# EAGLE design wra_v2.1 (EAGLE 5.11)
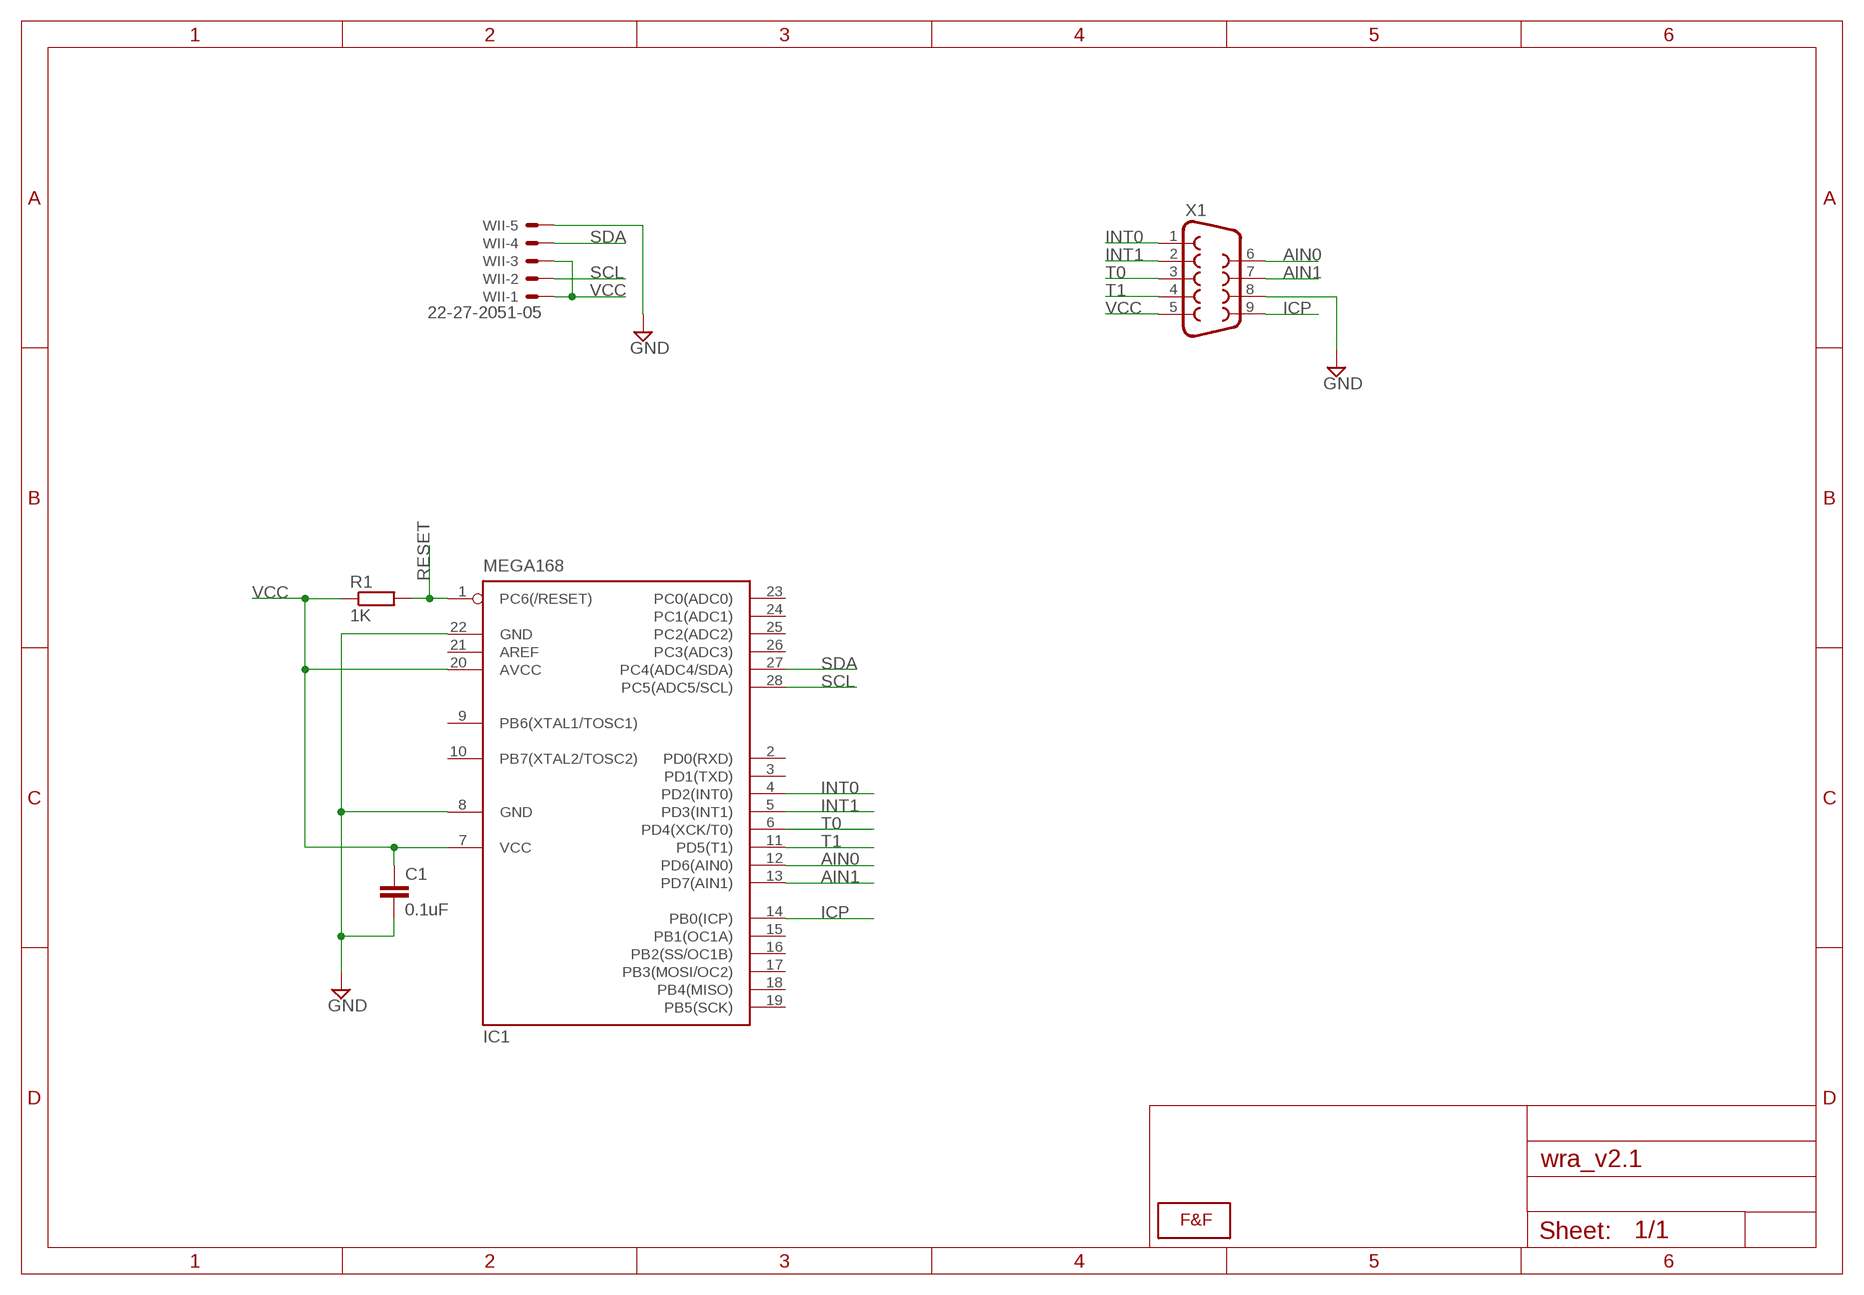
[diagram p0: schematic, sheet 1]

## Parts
C1  0.1uF  C-EU050-024X044  [C050-024X044]
IC1  MEGA168  MEGA8-P  [DIL28-3]
R1  1K  R-EU_0207/2V  [0207/2V]
U$1  LOGOLOGO_WITH_SMOKE_BIG  [LOGO_BIG]
WII  22-27-2051-05  [6410-05]
X1  DB9MALE  [DB9_MALE]

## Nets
AIN0: IC1.12(PD6(AIN0)) X1.6
AIN1: IC1.13(PD7(AIN1)) X1.7
GND: C1.2 IC1.8(GND) IC1.22(GND) WII.5 X1.8
ICP: IC1.14(PB0(ICP)) X1.9
INT0: IC1.4(PD2(INT0)) X1.1
INT1: IC1.5(PD3(INT1)) X1.2
RESET: IC1.1(PC6(/RESET)) R1.2
SCL: IC1.28(PC5(ADC5/SCL)) WII.2
SDA: IC1.27(PC4(ADC4/SDA)) WII.4
T0: IC1.6(PD4(XCK/T0)) X1.3
T1: IC1.11(PD5(T1)) X1.4
VCC: C1.1 IC1.7(VCC) IC1.20(AVCC) R1.1 WII.1 WII.3 X1.5
Unconnected: IC1.2(PD0(RXD)) IC1.3(PD1(TXD)) IC1.9(PB6(XTAL1/TOSC1)) IC1.10(PB7(XTAL2/TOSC2)) IC1.15(PB1(OC1A)) IC1.16(PB2(SS/OC1B)) IC1.17(PB3(MOSI/OC2)) IC1.18(PB4(MISO)) IC1.19(PB5(SCK)) IC1.21(AREF) IC1.23(PC0(ADC0)) IC1.24(PC1(ADC1)) IC1.25(PC2(ADC2)) IC1.26(PC3(ADC3))

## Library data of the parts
C1 = rcl:C-EU: CAPACITOR, European symbol
IC1 = atmel:MEGA8-P: MICROCONTROLLER 8 Kbytes FLASH, 1 kbytes SRAM, 512 bytes EEPROM, USART, 4-channel 10 bit ADC, 2-channel 8 bit ADC Pin compatible with Atmega48, ATMega88, ATMega168 Source: avr.lbr; OC_FARNELL: unknown; OC_NEWARK: unknown
R1 = rcl:R-EU_: RESISTOR, European symbol
U$1 = F&F:LOGO: Faísca e Fumaça Logo
WII = con-molex:22-?-05: CONNECTOR wire to board 2.54 mm (.1 inch) pitch header; OC_FARNELL: unknown; OC_NEWARK: unknown
X1 = SparkFun:DB9: DB9 Connector Standard DB9 (D-Sub 9) serial connector. Can be used for CAN bus as well as RS485 and RS232. Footprint production proven. Spark Fun Electronics SKU : PRT-00429

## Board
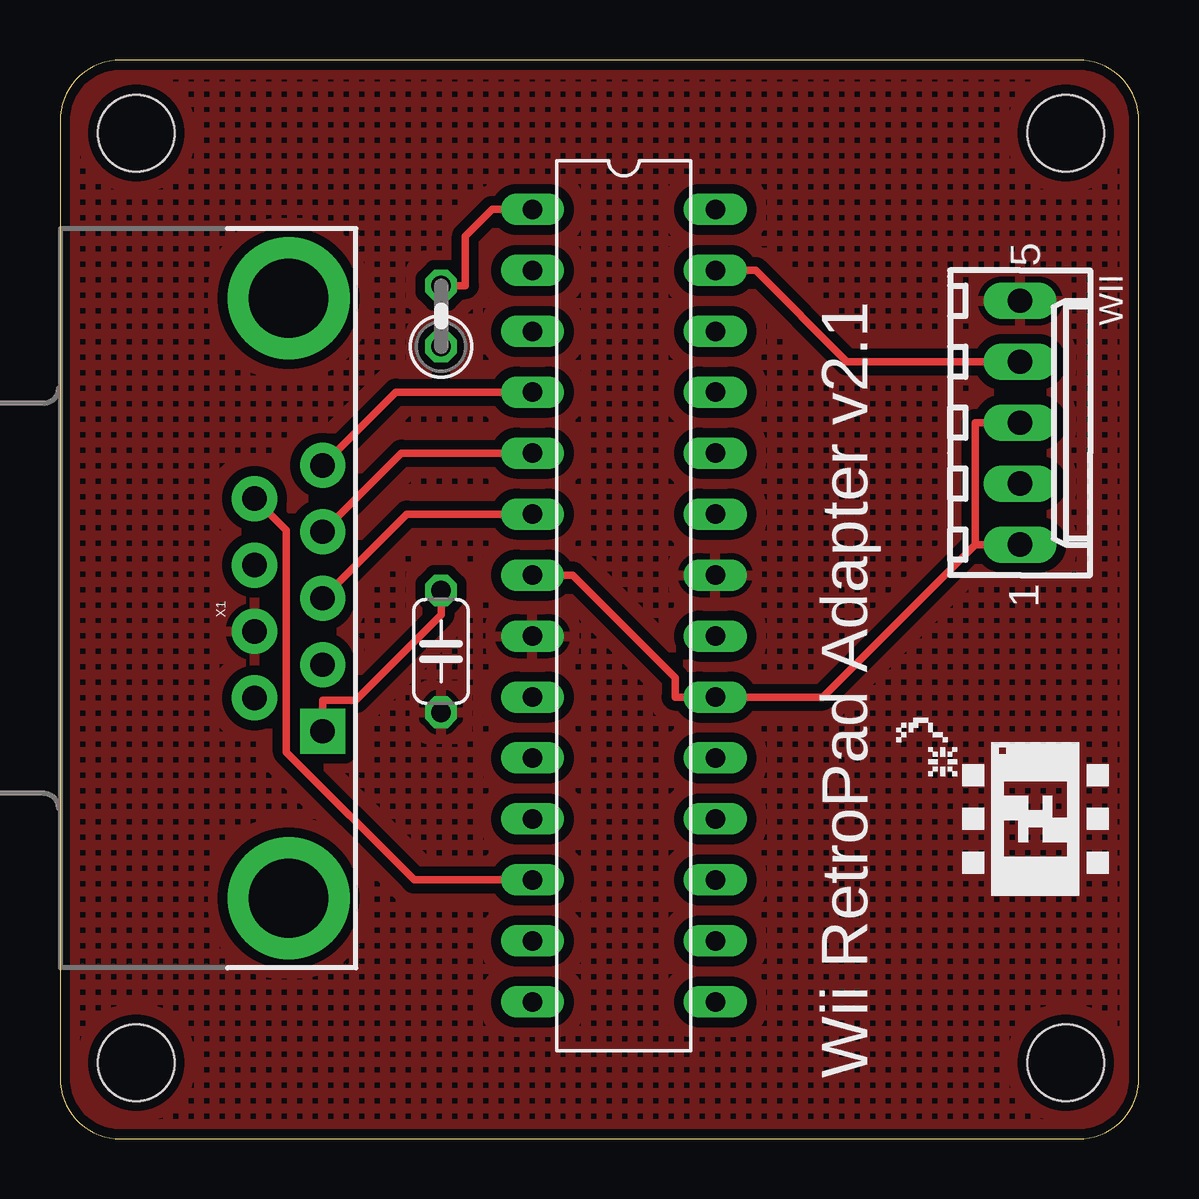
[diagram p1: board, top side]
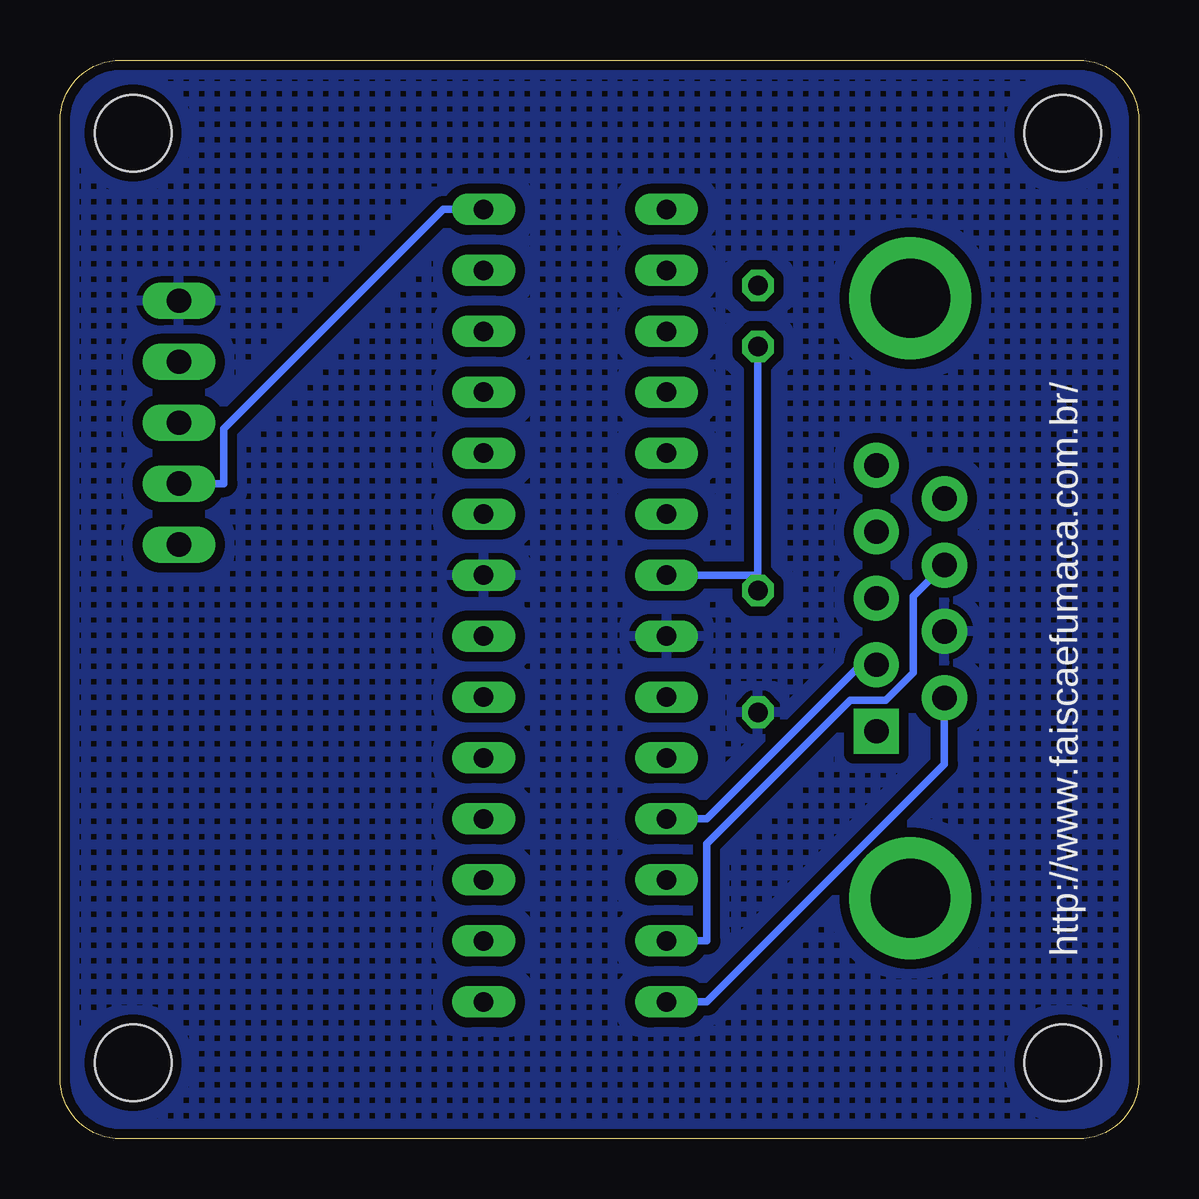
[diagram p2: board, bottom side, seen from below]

Size 44.96 x 44.96 mm. Coordinates in mm from the lower left corner, seen from the top.
Outline: 42.42,0 arc90 44.96,2.54 44.96,42.42 arc90 42.42,44.96 2.54,44.96 arc90 0,42.42 0,2.54 arc90 2.54,0 42.42,0
Copper layers (1*16): Top 0.035mm / dielectric 1.5mm / Bottom 0.035mm
Design rules "ITead_rule": minimum track width 6mil, minimum drill 12mil, track to track 6mil, track to pad 6mil, pad to pad 6mil, via to via 6mil, smd to smd 0mil, copper to edge 10mil, drill to drill 10mil, minimum pad ring 10mil, minimum via ring 6mil, stop-mask expansion 2mil, vias tented up to drill 100mil, thermal gap 10mil
Holes 3.2 mm at 3.17,41.91 3.17,3.17 41.91,3.17 41.91,41.91

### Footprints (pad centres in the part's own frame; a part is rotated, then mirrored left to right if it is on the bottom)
C050-024X044 = drill 0.813 octagon: 1 -2.54,0; 2 2.54,0
DIL28-3 = drill 0.813 long: 1 -16.51,-3.81; 2 -13.97,-3.81; 3 -11.43,-3.81; 4 -8.89,-3.81; 5 -6.35,-3.81; 6 -3.81,-3.81; 7 -1.27,-3.81; 8 1.27,-3.81; 9 3.81,-3.81; 10 6.35,-3.81; 11 8.89,-3.81; 12 11.43,-3.81; 13 13.97,-3.81; 14 16.51,-3.81; 15 16.51,3.81; 16 13.97,3.81; 17 11.43,3.81; 18 8.89,3.81; 19 6.35,3.81; 20 3.81,3.81; 21 1.27,3.81; 22 -1.27,3.81; 23 -3.81,3.81; 24 -6.35,3.81; 25 -8.89,3.81; 26 -11.43,3.81; 27 -13.97,3.81; 28 -16.51,3.81
0207/2V = drill 0.813 octagon: 1 -1.27,0; 2 1.27,0
6410-05 = drill 1.016 long: 1 5.08,0; 2 2.54,0; 3 0,0; 4 -2.54,0; 5 -5.08,0
DB9_MALE = drill 1.016 pad 1.88 round: 1 5.54,-1.42; 2 2.77,-1.42; 3 0,-1.42; 4 -2.77,-1.42; 6 4.15,1.42; 7 1.38,1.42; 8 -1.38,1.42; 9 -4.15,1.42 | drill 1.016 pad 1.88 square: 5 -5.54,-1.42 | drill 3.302 pad 5.08 round: G1 -12.5,0; G2 12.5,0

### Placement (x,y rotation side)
C1  15.88,20.32 270 top
IC1  23.5,22.23 270 top
R1  15.88,34.29 90 top
U$1  40.64,13.34 90 top
WII  40.01,29.84 270 top
X1  9.53,22.53 90 top

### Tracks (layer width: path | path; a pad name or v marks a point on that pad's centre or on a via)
AIN0
  Top 0.305: X1.6 9.43,25.36 9.43,16.12 14.75,10.79 IC1.12
AIN1
  Bottom 0.305: IC1.13 18.01,8.26 18.01,12.31 12.04,18.29 10.54,18.29 9.4,19.43 9.4,22.61 X1.7
GND
  pour Bottom (isolate 0.406, hatched): 0,44.45 44.45,44.45 44.45,0 0,0
  pour Top (isolate 0.406, hatched): 0,44.45 44.45,44.45 44.45,0 0,0
ICP
  Bottom 0.305: IC1.14 18.01,5.71 8.11,15.62 X1.9
INT0
  Top 0.305: X1.1 13.99,31.11 IC1.4
INT1
  Top 0.305: X1.2 14.22,28.57 IC1.5
RESET
  Top 0.305: IC1.1 18.01,38.73 16.89,37.62 16.89,35.56 R1.2
SCL
  Bottom 0.305: IC1.28 28.98,38.73 38.12,29.59 38.12,27.3 WII.2
SDA
  Top 0.305: IC1.27 28.98,36.2 32.79,32.38 WII.4
T0
  Top 0.305: X1.3 14.45,26.04 IC1.6
T1
  Bottom 0.305: IC1.11 18.01,13.34 11.58,19.76 X1.4
VCC
  Top 0.305: IC1.7 21.36,23.5 25.63,19.23 25.63,18.41 IC1.20 31.77,18.41 38.12,24.77 | C1.1 15.88,21.84 12.32,18.29 10.95,18.29 X1.5 | WII.3 38.12,29.84 38.12,24.77 | 38.12,24.77 WII.1
  Bottom 0.305: 15.88,23.5 R1.1 | C1.1 15.88,23.5 | 15.88,23.5 18.01,23.5 IC1.7

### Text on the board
tPlace: Wii RetroPad Adapter v2.1
bPlace: http://www.faiscaefumaca.com.br/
